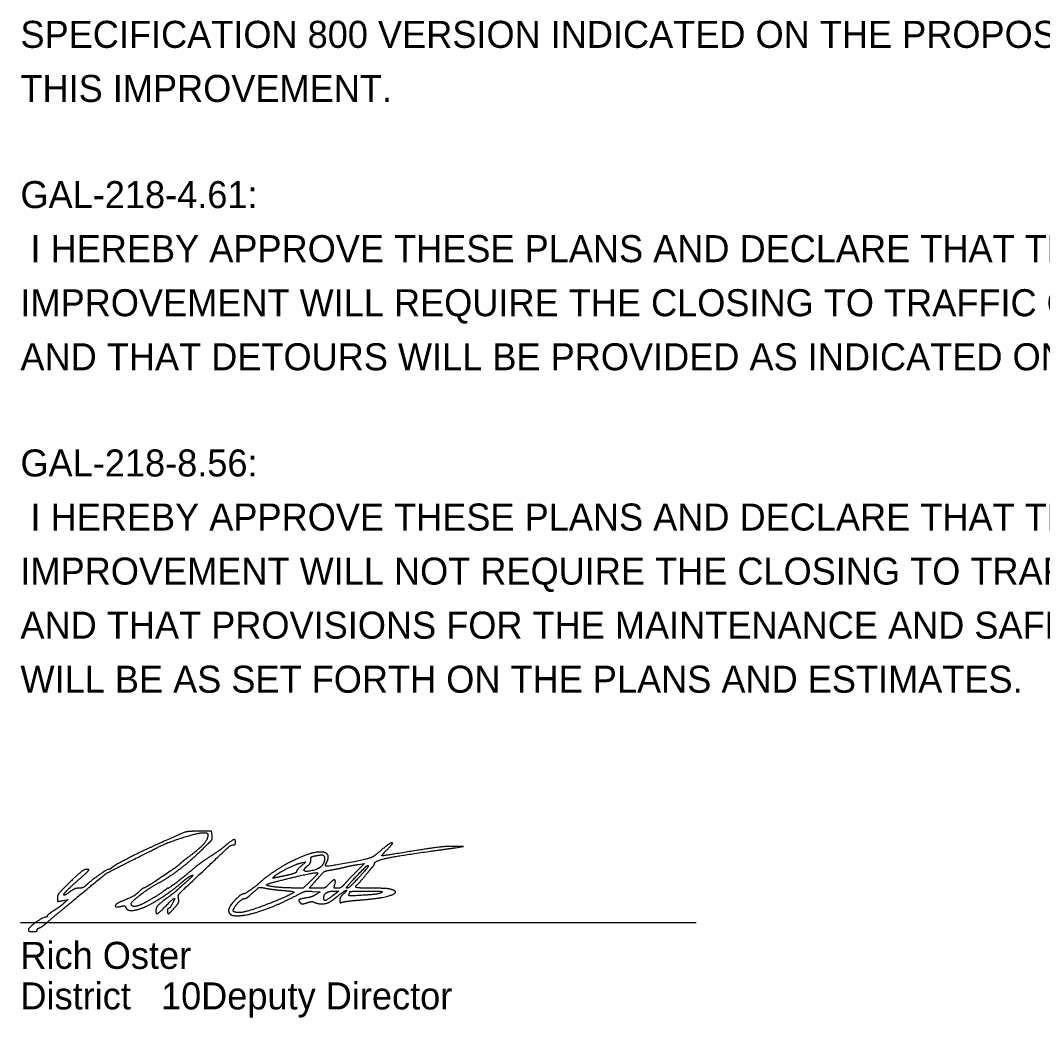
# Model space of a CAD drawing. Extents: x 0 to 34, y 0 to 22.
# Drawn here: x 24.53 to 29.82, y 5.64 to 10.81 of the extents above; entities that cross this region are included whole.
import ezdxf

# ---------------------------------------------------------------- set-up
doc = ezdxf.new("R2010")
doc.units = 0
doc.layers.add('SH_Data', color=7, linetype='Continuous')
doc.layers.add('SH_Text', color=7, linetype='Continuous')

msp = doc.modelspace()

# ---------------------------------------------------------------- linework, layer by layer
at = {"layer": 'SH_Data'}
for p, q in [((24.5279, 9.977), (24.5279, 9.977)), ((24.5279, 6.1367), (28.0279, 6.1367))]:
    msp.add_line(p, q, dxfattribs=at)
at = {"layer": 'SH_Text'}
msp.add_line((24.5693, 6.0996), (24.5693, 6.0996), dxfattribs=at)
for points in [[(25.5205, 6.5889), (25.518, 6.6107), (25.458, 6.61)], [(26.7818, 6.5241), (26.823, 6.53), (26.7853, 6.5309)], [(25.9831, 6.4461), (26.0055, 6.4514), (25.9812, 6.4291)], [(26.2781, 6.4376), (26.3106, 6.4423), (26.2668, 6.399)], [(26.0643, 6.3144), (26.0234, 6.3144), (26.0626, 6.359)], [(26.0316, 6.3524), (25.9924, 6.3144), (25.9389, 6.3154)], [(24.7474, 6.2502), (24.7755, 6.2552), (24.753, 6.2363)], [(26.0409, 6.298), (26.0801, 6.2957), (26.0587, 6.2817)], [(26.1518, 6.2994), (26.177, 6.2994), (26.1475, 6.2771)]]:
    msp.add_lwpolyline(points, dxfattribs=at)
for points in [[(25.1505, 6.4817), (25.2627, 6.538), (25.2883, 6.5493), (25.3605, 6.5739)], [(25.458, 6.61), (25.3955, 6.6093), (25.3691, 6.6011), (25.233, 6.5399)], [(25.3605, 6.5739), (25.4246, 6.5958), (25.4993, 6.6058), (25.4993, 6.5925)], [(25.4993, 6.5925), (25.4993, 6.5686), (25.4543, 6.5172), (25.3951, 6.4737)], [(25.4605, 6.5064), (25.5145, 6.5587), (25.5227, 6.57), (25.5205, 6.5889)], [(25.6418, 6.5507), (25.6418, 6.5687), (25.6242, 6.5638), (25.5925, 6.537)], [(25.233, 6.5399), (25.1528, 6.5039), (25.017, 6.4343), (25.0037, 6.4225)], [(25.3754, 6.3103), (25.5968, 6.5198), (25.6188, 6.5394), (25.6324, 6.5394)], [(25.5925, 6.537), (25.5763, 6.5233), (25.5394, 6.4968), (25.5105, 6.4782)], [(25.6324, 6.5394), (25.6376, 6.5394), (25.6418, 6.5445), (25.6418, 6.5507)], [(26.4286, 6.5151), (26.4654, 6.5519), (26.4359, 6.5465), (26.3929, 6.5086)], [(26.5253, 6.5011), (26.4049, 6.4816), (26.3963, 6.4828), (26.4286, 6.5151)], [(26.7853, 6.5309), (26.7409, 6.5321), (26.657, 6.5225), (26.5253, 6.5011)], [(26.6551, 6.5066), (26.7021, 6.5131), (26.7591, 6.5209), (26.7818, 6.5241)], [(24.7418, 6.2015), (24.9664, 6.3874), (24.9759, 6.394), (25.1505, 6.4817)], [(25.2372, 6.3385), (25.2909, 6.3669), (25.4056, 6.4531), (25.4605, 6.5064)], [(25.3951, 6.4737), (25.3802, 6.4627), (25.3621, 6.4478), (25.3548, 6.4405)], [(25.5105, 6.4782), (25.4817, 6.4596), (25.4479, 6.4356), (25.4355, 6.425)], [(26.0844, 6.5019), (26.0569, 6.5019), (25.9951, 6.4828), (25.9396, 6.4571)], [(26.0182, 6.433), (26.0257, 6.4384), (26.0318, 6.4506), (26.0318, 6.4602)], [(26.0318, 6.4602), (26.0318, 6.4736), (26.0371, 6.4786), (26.0552, 6.4822)], [(26.0552, 6.4822), (26.0681, 6.4848), (26.0833, 6.4869), (26.089, 6.4869)], [(26.1144, 6.4497), (26.1272, 6.4736), (26.1109, 6.5019), (26.0844, 6.5019)], [(26.089, 6.4869), (26.104, 6.4869), (26.102, 6.4441), (26.0862, 6.4275)], [(26.343, 6.4722), (26.3157, 6.4622), (26.1139, 6.4248), (26.1097, 6.429)], [(26.3929, 6.5086), (26.3737, 6.4916), (26.3513, 6.4753), (26.343, 6.4722)], [(26.3618, 6.4416), (26.3618, 6.456), (26.4844, 6.4832), (26.6551, 6.5066)], [(24.8621, 6.4106), (24.8541, 6.4093), (24.8186, 6.3799), (24.7834, 6.3453)], [(24.8524, 6.379), (24.8801, 6.4032), (24.8835, 6.4141), (24.8621, 6.4106)], [(24.9846, 6.4119), (24.9759, 6.4119), (24.8862, 6.3481), (24.8671, 6.3283)], [(25.0037, 6.4225), (24.9972, 6.4167), (24.9886, 6.4119), (24.9846, 6.4119)], [(25.3548, 6.4405), (25.34, 6.4257), (25.1732, 6.3144), (25.1659, 6.3144)], [(25.4355, 6.425), (25.3909, 6.3865), (25.2982, 6.3144), (25.2935, 6.3144)], [(25.9396, 6.4571), (25.8976, 6.4376), (25.7891, 6.3653), (25.7634, 6.3396)], [(25.8443, 6.3767), (25.8587, 6.3916), (25.9538, 6.4391), (25.9831, 6.4461)], [(25.9812, 6.4291), (25.9678, 6.4169), (25.9568, 6.4035), (25.9568, 6.3993)], [(26.0862, 6.4275), (26.0698, 6.4102), (25.9888, 6.3968), (25.9985, 6.413)], [(25.9985, 6.413), (26.0019, 6.4186), (26.0107, 6.4276), (26.0182, 6.433)], [(26.0626, 6.359), (26.095, 6.3958), (26.1072, 6.4044), (26.1324, 6.4084)], [(26.1097, 6.429), (26.1074, 6.4313), (26.1096, 6.4406), (26.1144, 6.4497)], [(26.1324, 6.4084), (26.1493, 6.411), (26.1816, 6.4176), (26.2043, 6.423)], [(26.2043, 6.423), (26.227, 6.4284), (26.2602, 6.435), (26.2781, 6.4376)], [(26.2196, 6.3144), (26.2118, 6.3144), (26.2332, 6.3396), (26.3042, 6.4139)], [(26.3288, 6.4324), (26.3322, 6.429), (26.3084, 6.4), (26.2558, 6.3436)], [(26.3042, 6.4139), (26.3158, 6.426), (26.3268, 6.4344), (26.3288, 6.4324)], [(26.3093, 6.3744), (26.3278, 6.3971), (26.3472, 6.4201), (26.3524, 6.4256)], [(26.3524, 6.4256), (26.3576, 6.431), (26.3618, 6.4382), (26.3618, 6.4416)], [(24.7524, 6.2788), (24.7487, 6.2825), (24.7956, 6.3295), (24.8524, 6.379)], [(25.3643, 6.3447), (25.3787, 6.3573), (25.3969, 6.3713), (25.4046, 6.3756)], [(25.4046, 6.3756), (25.4253, 6.3872), (25.4127, 6.3694), (25.3802, 6.3412)], [(25.8518, 6.3691), (25.835, 6.3655), (25.8342, 6.3663), (25.8443, 6.3767)], [(25.9137, 6.3825), (25.8899, 6.3773), (25.8621, 6.3713), (25.8518, 6.3691)], [(25.8571, 6.3501), (25.9539, 6.3749), (26.0634, 6.3978), (26.0672, 6.394)], [(25.9568, 6.3993), (25.9568, 6.3952), (25.9374, 6.3876), (25.9137, 6.3825)], [(26.0672, 6.394), (26.0692, 6.392), (26.0531, 6.3733), (26.0316, 6.3524)], [(26.1562, 6.3332), (26.1624, 6.3579), (26.1464, 6.3579), (26.1229, 6.3331)], [(26.2668, 6.399), (26.2428, 6.3751), (26.2155, 6.3463), (26.2062, 6.335)], [(26.2699, 6.3307), (26.273, 6.3321), (26.2907, 6.3517), (26.3093, 6.3744)], [(24.7834, 6.3453), (24.737, 6.2999), (24.7193, 6.2773), (24.7193, 6.2639)], [(24.831, 6.3144), (24.818, 6.3144), (24.7972, 6.306), (24.7823, 6.2946)], [(24.8671, 6.3283), (24.8597, 6.3207), (24.8435, 6.3144), (24.831, 6.3144)], [(25.1018, 6.2345), (25.1018, 6.244), (25.1976, 6.3176), (25.2372, 6.3385)], [(25.1659, 6.3144), (25.1633, 6.3144), (25.152, 6.306), (25.1409, 6.2957)], [(25.155, 6.2107), (25.1921, 6.2235), (25.3186, 6.3045), (25.3643, 6.3447)], [(25.2796, 6.3068), (25.265, 6.2945), (25.2172, 6.264), (25.1804, 6.2435)], [(25.2935, 6.3144), (25.2908, 6.3144), (25.2846, 6.311), (25.2796, 6.3068)], [(25.3411, 6.306), (25.3342, 6.2992), (25.3097, 6.2798), (25.2867, 6.2628)], [(25.3802, 6.3412), (25.3656, 6.3285), (25.348, 6.3127), (25.3411, 6.306)], [(25.347, 6.2607), (25.3441, 6.276), (25.3498, 6.286), (25.3754, 6.3103)], [(25.7634, 6.3396), (25.7481, 6.3243), (25.6888, 6.2844), (25.6813, 6.2844)], [(25.7135, 6.2752), (25.7577, 6.3154), (25.7686, 6.3205), (25.7974, 6.3143)], [(25.7974, 6.3143), (25.8129, 6.311), (25.8537, 6.3059), (25.8881, 6.303)], [(25.8022, 6.3315), (25.8002, 6.3335), (25.8249, 6.3419), (25.8571, 6.3501)], [(25.9389, 6.3154), (25.8837, 6.3163), (25.8085, 6.3252), (25.8022, 6.3315)], [(25.8881, 6.303), (25.9225, 6.3001), (25.9478, 6.2953), (25.9443, 6.2924)], [(26.1229, 6.3331), (26.1083, 6.3177), (26.0981, 6.3144), (26.0643, 6.3144)], [(26.1704, 6.3144), (26.154, 6.3144), (26.1521, 6.3169), (26.1562, 6.3332)], [(26.2062, 6.335), (26.1959, 6.3224), (26.182, 6.3144), (26.1704, 6.3144)], [(26.1728, 6.275), (26.2054, 6.3014), (26.2247, 6.3059), (26.1968, 6.2807)], [(26.2558, 6.3436), (26.2408, 6.3276), (26.2245, 6.3144), (26.2196, 6.3144)], [(26.2643, 6.3213), (26.2643, 6.3251), (26.2668, 6.3293), (26.2699, 6.3307)], [(26.3449, 6.3143), (26.3006, 6.3144), (26.2643, 6.3175), (26.2643, 6.3213)], [(26.2943, 6.2541), (26.4055, 6.2627), (26.4942, 6.2958), (26.4427, 6.3096)], [(26.4427, 6.3096), (26.4333, 6.3122), (26.3893, 6.3143), (26.3449, 6.3143)], [(24.7193, 6.2639), (24.7193, 6.2465), (24.7211, 6.2456), (24.7474, 6.2502)], [(24.7823, 6.2946), (24.7681, 6.2837), (24.7546, 6.2766), (24.7524, 6.2788)], [(25.1409, 6.2957), (25.1217, 6.2779), (25.1072, 6.2699), (25.0512, 6.2461)], [(25.2867, 6.2628), (25.2468, 6.2333), (25.2293, 6.2126), (25.2293, 6.1949)], [(25.2792, 6.2207), (25.3176, 6.2596), (25.3317, 6.2643), (25.3133, 6.232)], [(25.3267, 6.2142), (25.3443, 6.2343), (25.3497, 6.2465), (25.347, 6.2607)], [(25.6813, 6.2844), (25.6704, 6.2844), (25.6133, 6.226), (25.608, 6.2094)], [(25.6353, 6.2119), (25.645, 6.2306), (25.6793, 6.2613), (25.691, 6.2617)], [(25.6524, 6.1719), (25.702, 6.1719), (25.8613, 6.227), (25.9586, 6.2778)], [(25.691, 6.2617), (25.6954, 6.2618), (25.7055, 6.2679), (25.7135, 6.2752)], [(25.9443, 6.2924), (25.9348, 6.2843), (25.8329, 6.2404), (25.7693, 6.2171)], [(25.9586, 6.2778), (25.9934, 6.296), (26.0091, 6.2998), (26.0409, 6.298)], [(26.0081, 6.2638), (25.9766, 6.2596), (25.9656, 6.2502), (25.9778, 6.238)], [(26.0587, 6.2817), (26.0469, 6.274), (26.0241, 6.266), (26.0081, 6.2638)], [(26.0993, 6.2645), (26.0993, 6.2819), (26.1257, 6.2994), (26.1518, 6.2994)], [(26.1475, 6.2771), (26.1155, 6.2529), (26.0993, 6.2487), (26.0993, 6.2645)], [(26.1255, 6.2413), (26.1338, 6.2455), (26.1551, 6.2607), (26.1728, 6.275)], [(26.1968, 6.2807), (26.1886, 6.2732), (26.1818, 6.2605), (26.1818, 6.2524)], [(26.1818, 6.2524), (26.1818, 6.2406), (26.1851, 6.2387), (26.1987, 6.2429)], [(26.1987, 6.2429), (26.2079, 6.2457), (26.251, 6.2508), (26.2943, 6.2541)], [(26.3045, 6.2779), (26.241, 6.2739), (26.2273, 6.2749), (26.2304, 6.2831)], [(26.2304, 6.2831), (26.2326, 6.2886), (26.2343, 6.2946), (26.2343, 6.2963)], [(26.2343, 6.2963), (26.2343, 6.298), (26.2739, 6.2993), (26.3224, 6.2992)], [(26.3965, 6.2908), (26.3888, 6.2864), (26.3474, 6.2805), (26.3045, 6.2779)], [(26.3224, 6.2992), (26.3895, 6.299), (26.4072, 6.297), (26.3965, 6.2908)], [(24.6593, 6.1317), (24.6696, 6.141), (24.7067, 6.1724), (24.7418, 6.2015)], [(24.6987, 6.197), (24.6811, 6.1857), (24.6668, 6.1737), (24.6668, 6.1704)], [(24.753, 6.2363), (24.7407, 6.226), (24.7162, 6.2082), (24.6987, 6.197)], [(25.0512, 6.2461), (25.0199, 6.2329), (25.0178, 6.2138), (25.0483, 6.2205)], [(25.0483, 6.2205), (25.064, 6.2239), (25.0711, 6.222), (25.0744, 6.2136)], [(25.0744, 6.2136), (25.0798, 6.1995), (25.1185, 6.1981), (25.155, 6.2107)], [(25.1804, 6.2435), (25.1433, 6.2228), (25.1018, 6.218), (25.1018, 6.2345)], [(25.2293, 6.1949), (25.2293, 6.1788), (25.2468, 6.1878), (25.2792, 6.2207)], [(25.2893, 6.1982), (25.2893, 6.18), (25.3011, 6.1851), (25.3267, 6.2142)], [(25.2949, 6.2095), (25.2918, 6.2095), (25.2893, 6.2044), (25.2893, 6.1982)], [(25.3133, 6.232), (25.3063, 6.2196), (25.298, 6.2095), (25.2949, 6.2095)], [(25.608, 6.2094), (25.6053, 6.2007), (25.6071, 6.1888), (25.6121, 6.1828)], [(25.6362, 6.1918), (25.6291, 6.1947), (25.6289, 6.1995), (25.6353, 6.2119)], [(25.7693, 6.2171), (25.712, 6.1961), (25.653, 6.1849), (25.6362, 6.1918)], [(25.9778, 6.238), (25.983, 6.2328), (25.994, 6.2331), (26.0122, 6.2392)], [(26.0122, 6.2392), (26.0269, 6.244), (26.0429, 6.2456), (26.0476, 6.2427)], [(26.0476, 6.2427), (26.0617, 6.234), (26.1094, 6.2331), (26.1255, 6.2413)], [(24.6592, 6.1644), (24.645, 6.1644), (24.5693, 6.1099), (24.5693, 6.0996)], [(24.6668, 6.1704), (24.6668, 6.1671), (24.6634, 6.1644), (24.6592, 6.1644)], [(25.6121, 6.1828), (25.6173, 6.1765), (25.6342, 6.1719), (25.6524, 6.1719)], [(24.5693, 6.0996), (24.5693, 6.0933), (24.5778, 6.0894), (24.5918, 6.0894)], [(24.5918, 6.0894), (24.6042, 6.0894), (24.6143, 6.0929), (24.6143, 6.0972)], [(24.6143, 6.0972), (24.6143, 6.1014), (24.6202, 6.1071), (24.6274, 6.1098)], [(24.6274, 6.1098), (24.6346, 6.1125), (24.649, 6.1223), (24.6593, 6.1317)]]:
    msp.add_open_spline(points, degree=2, dxfattribs=at)

# ---------------------------------------------------------------- texts
at = {"layer": 'SH_Data'}
for s, p in [(' I HEREBY APPROVE THESE PLANS AND DECLARE THAT THE MAKING OF THIS', (24.5279, 9.557)), ('IMPROVEMENT WILL REQUIRE THE CLOSING TO TRAFFIC OF THE HIGHWAY', (24.5279, 9.277)), ('AND THAT DETOURS WILL BE PROVIDED AS INDICATED ON SHEET 6.', (24.5279, 8.997)), (' I HEREBY APPROVE THESE PLANS AND DECLARE THAT THE MAKING OF THIS', (24.5279, 8.167)), ('IMPROVEMENT WILL NOT REQUIRE THE CLOSING TO TRAFFIC OF THE HIGHWAY', (24.5279, 7.887)), ('AND THAT PROVISIONS FOR THE MAINTENANCE AND SAFETY OF TRAFFIC', (24.5279, 7.607)), ('WILL BE AS SET FORTH ON THE PLANS AND ESTIMATES.', (24.5279, 7.327))]:
    msp.add_text(s, height=0.14, dxfattribs=at).set_placement(p)
at = {"layer": 'SH_Text'}
for s, p in [('SPECIFICATION 800 VERSION INDICATED ON THE PROPOSAL SHALL GOVERN', (24.5279, 10.667)), ('THIS IMPROVEMENT.', (24.5279, 10.387)), ('GAL-218-4.61:', (24.5279, 9.837)), ('GAL-218-8.56:', (24.5279, 8.447)), ('Rich Oster', (24.5279, 5.8967)), ('District       Deputy Director', (24.5279, 5.6867)), ('              10', (24.5279, 5.6867))]:
    msp.add_text(s, height=0.14, dxfattribs=at).set_placement(p)

doc.saveas('drawing.dxf')
